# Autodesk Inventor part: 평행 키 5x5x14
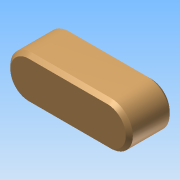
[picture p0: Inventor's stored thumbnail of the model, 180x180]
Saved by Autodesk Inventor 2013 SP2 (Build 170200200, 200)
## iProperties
Created: 2026-07
Part Number: 평행 키 5x5x14
Material: Generic
Document SubType Name: Modeling
Designer: aa
Density: 1 g/cm^3
변환 표준: STEP AP214IS
전처리기: Build: 200, Release: 2013 SP2 Update 6 - Date: Thu 07/17/2014
전송 단위: 밀리미터
불확실성: 0.01
Author: aa
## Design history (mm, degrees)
node "평행 키 5x5x141"
node "솔리드1"
node "기준1"
